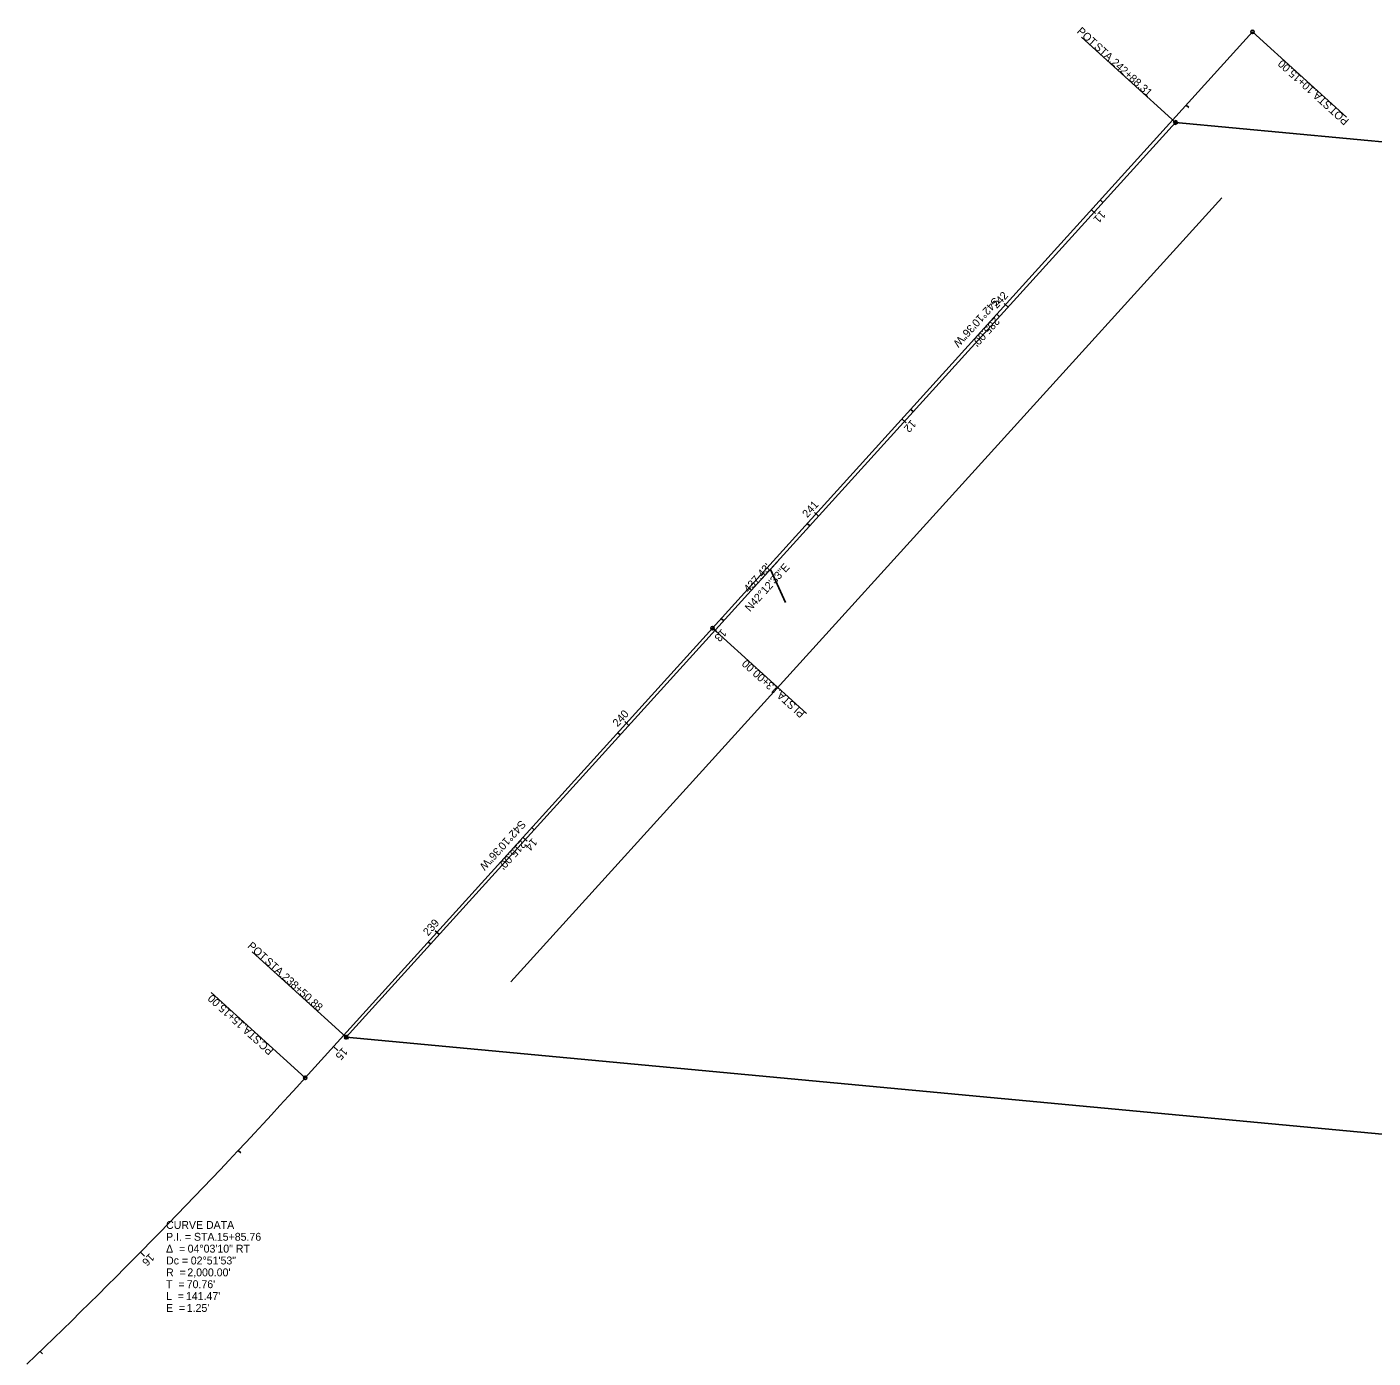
# Model space of a CAD drawing. Extents: x 1538200 to 1540847, y 661118 to 663597.
# Drawn here: x 1539994.5 to 1540471.5, y 663125.5 to 663597 of the extents above; entities that cross this region are included whole.
import ezdxf

# ---------------------------------------------------------------- set-up
doc = ezdxf.new("R2010")
doc.units = 0
for name, color, linetype in [('DT_X_Break_Line', 7, 'Continuous'), ('DT_X_Contour_Major', 7, 'Continuous'), ('DT_X_Contour_Minor', 7, 'Continuous'), ('DT_X_Contour_Text', 7, 'Continuous'), ('DT_X_Island', 7, 'Continuous'), ('DT_X_Terrain_Boundary', 7, 'Continuous'), ('DT_X_Triangles', 7, 'Continuous'), ('DT_X_Void', 7, 'Continuous'), ('RS_Raster1', 7, 'Continuous')]:
    doc.layers.add(name, color=color, linetype=linetype)

msp = doc.modelspace()

# ---------------------------------------------------------------- linework, layer by layer
at = {"layer": 'DT_X_Break_Line'}
for p, q in [((1540375.83, 663534.73), (1540374.94, 663535.54)), ((1540342.24, 663497.7), (1540340.76, 663499.04)), ((1540308.65, 663460.66), (1540307.76, 663461.47)), ((1540275.06, 663423.63), (1540273.58, 663424.97)), ((1540241.46, 663386.59), (1540240.58, 663387.4)), ((1540207.87, 663349.56), (1540206.39, 663350.9)), ((1540174.28, 663312.53), (1540173.39, 663313.33)), ((1540140.69, 663275.49), (1540139.21, 663276.83))]:
    msp.add_line(p, q, dxfattribs=at)
at = {"layer": 'DT_X_Contour_Major'}
for p, q in [((1540401.57, 663563.11), (1540368.24, 663593.34)), ((1540107.69, 663239.11), (1540074.36, 663269.34))]:
    msp.add_line(p, q, dxfattribs=at)
for centre in [(1540401.57, 663563.11), (1540107.69, 663239.11)]:
    msp.add_circle(centre, 0.6, dxfattribs=at)
at = {"layer": 'DT_X_Contour_Minor'}
msp.add_line((1540107.69, 663239.11), (1540401.57, 663563.11), dxfattribs=at)
at = {"layer": 'DT_X_Island'}
for p, q in [((1540428.82, 663595.21), (1540237.46, 663384)), ((1540428.82, 663595.21), (1540462.17, 663565)), ((1540405.32, 663569.27), (1540406.21, 663568.47)), ((1540166.01, 663258.75), (1540417.91, 663536.47)), ((1540371.75, 663532.22), (1540373.23, 663530.88)), ((1540338.18, 663495.17), (1540339.06, 663494.36)), ((1540304.6, 663458.11), (1540306.09, 663456.77)), ((1540271.03, 663421.06), (1540271.92, 663420.25)), ((1540237.46, 663384), (1540093.11, 663224.67)), ((1540237.46, 663384), (1540270.81, 663353.79)), ((1540237.46, 663384), (1540238.94, 663382.66)), ((1540203.89, 663346.95), (1540204.78, 663346.15)), ((1540170.32, 663309.9), (1540171.8, 663308.55)), ((1540136.75, 663272.84), (1540137.64, 663272.04)), ((1540093.14, 663224.71), (1540059.79, 663254.92)), ((1540103.18, 663235.79), (1540104.66, 663234.45)), ((1540069.41, 663198.97), (1540070.29, 663198.15)), ((1540034.75, 663162.95), (1540036.17, 663161.54)), ((1539999.19, 663127.79), (1540000.02, 663126.93))]:
    msp.add_line(p, q, dxfattribs=at)
for centre in [(1540428.82, 663595.21), (1540237.46, 663384), (1540093.14, 663224.71)]:
    msp.add_circle(centre, 0.6, dxfattribs=at)
msp.add_arc((1538610.98, 664567.54), 2000, 313.77053, 317.82331, dxfattribs=at)
at = {"layer": 'DT_X_Terrain_Boundary'}
for p, q in [((1540400.7, 663563.46), (1540402.45, 663562.76)), ((1540401.22, 663562.24), (1540401.92, 663563.99)), ((1540106.96, 663239.71), (1540108.42, 663238.51)), ((1540108.29, 663239.83), (1540107.09, 663238.38))]:
    msp.add_line(p, q, dxfattribs=at)
at = {"layer": 'DT_X_Triangles'}
msp.add_line((1540401.57, 663563.11), (1540846.87, 663521.4), dxfattribs=at)
at = {"layer": 'RS_Raster1'}
for p, q in [((1540107.69, 663239.11), (1540401.57, 663563.11)), ((1540254.92, 663401.43), (1540261, 663408.13)), ((1540257.96, 663404.78), (1540263.36, 663393.03)), ((1540107.69, 663239.11), (1540814.23, 663172.92))]:
    msp.add_line(p, q, dxfattribs=at)

# ---------------------------------------------------------------- texts
at = {"layer": 'DT_X_Break_Line'}
for s, p in [('242', (1540338.23, 663497)), ('241', (1540271.04, 663422.92)), ('240', (1540203.83, 663348.82)), ('239', (1540136.67, 663274.78))]:
    msp.add_text(s, height=2.8, rotation=47.7909, dxfattribs=at).set_placement(p)
at = {"layer": 'DT_X_Contour_Major'}
for s, p in [('POT', (1540366.37, 663595.09)), (' STA. ', (1540371.65, 663590.3)), ('242+88.31', (1540378.56, 663584.03)), ('POT', (1540072.47, 663271.1)), (' STA. ', (1540077.75, 663266.31)), ('238+50.88', (1540084.65, 663260.05))]:
    msp.add_text(s, height=2.8, rotation=317.7909, dxfattribs=at).set_placement(p)
at = {"layer": 'DT_X_Contour_Text'}
msp.add_text('N42°12\'33"E', height=2.8, rotation=47.7909, dxfattribs=at).set_placement((1540250.72, 663389.65))
at = {"layer": 'DT_X_Island'}
for s, rotation, p in [('10+15.00', 137.8233, (1540451.05, 663575.02)), (' STA. ', 137.8233, (1540457.96, 663568.76)), ('POT', 137.8233, (1540463.24, 663563.97)), ('11', 227.8233, (1540375.01, 663532.1)), ('S42°10\'36"W', 227.8233, (1540337.39, 663501.44)), ("285.00'", 227.8233, (1540337.49, 663494.35)), ('12', 227.8233, (1540307.86, 663457.99)), ('13', 227.8233, (1540240.71, 663383.87)), ('13+00.00', 137.8233, (1540261.11, 663362.53)), (' STA. ', 137.8233, (1540268.02, 663356.27)), ('PI', 137.8233, (1540270.47, 663354.05)), ('S42°10\'36"W', 227.8233, (1540169.53, 663316.17)), ("215.00'", 227.8233, (1540169.63, 663309.08)), ('14', 227.8233, (1540173.63, 663309.82)), ('15+15.00', 137.8233, (1540071.84, 663243.95)), (' STA. ', 137.8233, (1540078.75, 663237.69)), ('PC', 137.8233, (1540082.16, 663234.6)), ('15', 227.8233, (1540106.43, 663235.66)), ('16', 225.3882, (1540038.03, 663162.71))]:
    msp.add_text(s, height=2.8, rotation=rotation, dxfattribs=at).set_placement(p)
for s, p in [('CURVE DATA', (1540043.83, 663171.21)), ('P.I. = STA. ', (1540043.83, 663167.01)), ('15+85.76', (1540061.82, 663167.01)), ('Δ  = ', (1540043.83, 663162.81)), ('Dc = ', (1540043.83, 663158.61)), ('04°03\'10" RT', (1540051.48, 663162.81)), ('02°51\'53"', (1540052.58, 663158.61)), ('R  = ', (1540043.83, 663154.41)), ("2,000.00'", (1540051.37, 663154.41)), ('T  = ', (1540043.83, 663150.21)), ("70.76'", (1540051.15, 663150.21)), ('L  = ', (1540043.83, 663146.01)), ("141.47'", (1540050.87, 663146.01)), ('E  = ', (1540043.83, 663141.81)), ("1.25'", (1540051.17, 663141.81))]:
    msp.add_text(s, height=2.8, dxfattribs=at).set_placement(p)
at = {"layer": 'DT_X_Void'}
msp.add_text("437.43'", height=2.8, rotation=47.7909, dxfattribs=at).set_placement((1540250.28, 663396.37))

doc.saveas('drawing.dxf')
